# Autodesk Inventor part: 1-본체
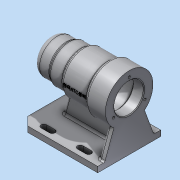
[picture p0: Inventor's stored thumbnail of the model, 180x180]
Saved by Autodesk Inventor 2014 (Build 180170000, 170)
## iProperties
Created: 2017-09
Part Number: 1-본체
Material: Aluminum 6061
Document SubType Name: Modeling
Designer: user
Density: 2.71 g/cm^3
Appearance: Aluminum - Flat
Mass: 697.162 g
Surface Area: 710.877 cm^2
Volume: 257.255 cm^3
Author: user
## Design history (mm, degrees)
sketch "Sketch1"
  geometry: L1 (0, 0)-(25, 0); L2 (25, 0)-(25, 25); L3 (25, 25)-(0, 25); L4 (0, 25)-(0, 0); L5 (25, 0)-(45, 0); L6 (45, 0)-(45, 27); L7 (45, 27)-(25, 27); L8 (25, 27)-(25, 0); L9 (45, 0)-(84, 0); L10 (84, 0)-(84, 30); L11 (84, 30)-(45, 30); L12 (45, 30)-(45, 0); L13 (84, 0)-(112, 0); L14 (112, 0)-(112, 34); L15 (112, 34)-(84, 34); L16 (84, 34)-(84, 0)
  constraints: 32 end point, 8 parallel, 4 horizontal, 4 perpendicular
  dimensions: "d0" = 25 distance between parallel lines of L2 L4; "d1" = 45 distance between parallel lines of L6 L4; "d2" = 84 distance between parallel lines of L10 L4; "d3" = 112 distance between parallel lines of L14 L4; "d4" = 60 diameter of L11 L9; "d5" = 54 diameter of L7 L5; "d6" = 50 diameter of L3 L1; "d7" = 68 diameter of L15 L13
revolve "Revolution1" sketch "Sketch1" stored, may be unused: angle "d8" = 90 deg
workplane "Work Plane1"
sketch "Sketch2"
  geometry: L1 (0, -45)-(-112, -45); L2 (-112, -45)-(-112, 45); L3 (-112, 45)-(0, 45); L4 (0, 45)-(0, -45); L5 (-112, 34)-(-112, -34) reference; 3 further points
  constraints: 8 end point, 3 midpoint, 2 parallel, 1 coincident, 1 horizontal, 1 perpendicular
  dimensions: "d10" = 112 distance of L1.start L1.end; "d11" = 90 distance of L1.end L2.end
extrude "Extrusion1" join sketch "Sketch2" distance "d12" = 8; taper "d13" = 0 deg
sketch "Sketch3"
  geometry: L1 (0, 45)-(0, -45) reference; L2 (112, -45)-(112, 45) reference; L3 (22, 4)-(112, 4); L4 (112, 4)-(112, -4); L5 (112, -4)-(22, -4); L6 (22, -4)-(22, 4); 2 further points
  constraints: 8 end point, 2 midpoint, 2 parallel, 1 horizontal, 1 perpendicular, 1 point on line
  dimensions: "d14" = 22 distance between parallel lines of L6 L1; "d15" = 8 distance of L5.end L3.start
extrude "Extrusion2" join sketch "Sketch3" stored distance "d16" = 8; taper "d17" = 0 deg
feature "FaceDraft1" dims angle "d18" = 15 deg
sketch "Sketch4"
  geometry: L1 (90, 0)-(90, 8) reference; L2 (49, 8)-(90, 8) reference; L3 (41, 8)-(41, 36.236) reference; L4 (0, 8)-(41, 8) reference; L5 (0, 0)-(0, 8) reference; L6 (10, 8)-(23.1, 43.992); L7 (80, 8)-(66.9, 43.992); L8 (49, 8)-(49, 36.236) reference; A1 r 34 centre (45, 70) between (49, 36.236) and (41, 36.236) reference
  constraints: 4 end point, 2 point on circle, 2 point on line
  dimensions: "d19" = 110 deg angle of L7 L2; "d20" = 110 deg angle of L4 L6; "d21" = 10 distance from line of L6.start L5; "d22" = 10 distance from line of L7.start L1
extrude "Extrusion5" join sketch "Sketch4" distance "d27" = 8; taper "d28" = 0 deg
chamfer "Chamfer1" distance "d29" = 12; stored, may be unused: second distance "d30" = 2, angle "d31" = 45 deg
sketch "Sketch5"
  geometry: L1 (112, -45)-(112, -35) reference; L2 (112, 45)-(12, 45) reference; L3 (76, -34)-(88, -34); L4 (76, -38)-(88, -38); L5 (88, -30)-(76, -30); L6 (24, -34)-(36, -34); L7 (36, -30)-(24, -30); L8 (24, -38)-(36, -38); L9 (76, 30)-(88, 30); L10 (76, 34)-(88, 34); L11 (88, 38)-(76, 38); L12 (24, 34)-(36, 34); L13 (24, 30)-(36, 30); L14 (36, 38)-(24, 38); A1 r 4 centre (76, -34) between (76, -30) and (76, -38); A2 r 4 centre (88, -34) between (88, -38) and (88, -30); A3 r 4 centre (36, -34) between (36, -38) and (36, -30); A4 r 4 centre (24, -34) between (24, -30) and (24, -38); A5 r 4 centre (76, 34) between (76, 38) and (76, 30); A6 r 4 centre (88, 34) between (88, 30) and (88, 38); A7 r 4 centre (36, 34) between (36, 30) and (36, 38); A8 r 4 centre (24, 34) between (24, 38) and (24, 30); 5 further points
  constraints: 32 end point, 16 point on circle, 16 tangent, 8 centre point, 5 horizontal alignment, 5 parallel, 4 midpoint, 2 vertical alignment
  dimensions: "d32" = 12 distance of L3.start L3.end; "d33" = 8 distance between parallel lines of L4 L5; "d34" = 12 distance of L6.start L6.end; "d35" = 8 distance between parallel lines of L8 L7; "d36" = 12 distance of L10.start L10.end; "d37" = 8 distance between parallel lines of L9 L11; "d38" = 12 distance of L12.start L12.end; "d39" = 8 distance between parallel lines of L13 L14; "d40" = 34 vertical distance of L12.start point (0, 0); "d41" = 34 vertical distance of L6.start point (0, 0); "d42" = 40 distance of L3.start L6.end; "d43" = 24 distance from line of L3.end L1
extrude "Extrusion6" cut sketch "Sketch5" stored distance "d44" = 8; taper "d45" = 0 deg
sketch "Sketch6"
  geometry: L1 (6, 10.5)-(9, 10.5); L2 (9, 10.5)-(9, 0); L3 (9, 0)-(6, 0); L4 (6, 0)-(6, 10.5); L5 (9, 0)-(13, 0); L6 (13, 0)-(13, 16); L7 (13, 16)-(9, 16); L8 (9, 16)-(9, 0); L9 (13, 0)-(31, 0); L10 (31, 0)-(31, 17.5); L11 (31, 17.5)-(13, 17.5); L12 (13, 17.5)-(13, 0); L13 (31, 0)-(43, 0); L14 (43, 0)-(43, 21); L15 (43, 21)-(31, 21); L16 (31, 21)-(31, 0); L17 (43, 0)-(97, 0); L18 (97, 0)-(97, 24); L19 (97, 24)-(43, 24); L20 (43, 24)-(43, 0); L21 (97, 0)-(112, 0); L22 (112, 0)-(112, 21); L23 (112, 21)-(97, 21); L24 (97, 21)-(97, 0); L25 (112, -26.008)-(112, 34) reference; 1 further point
  constraints: 48 end point, 12 parallel, 7 horizontal alignment, 6 horizontal, 6 perpendicular, 1 point on line
  dimensions: "d46" = 18 distance between parallel lines of L10 L12; "d47" = 12 distance between parallel lines of L14 L10; "d48" = 54 distance between parallel lines of L18 L20; "d49" = 15 distance between parallel lines of L22 L18; "d50" = 4 distance between parallel lines of L12 L8; "d51" = 3 distance between parallel lines of L8 L4; "d52" = 42 diameter of L23 L21; "d53" = 48 diameter of L19 L17; "d54" = 42 diameter of L15 L13; "d55" = 35 diameter of L11 L9; "d56" = 32 diameter of L7 L5; "d57" = 21 diameter of L1 L3; "d59" = 13 distance from line of L25.end L23
revolve "Revolution2" sketch "Sketch6" stored, may be unused: angle "d58" = 90 deg
fillet "Fillet1" dims "d60" = 9
fillet "Fillet2" dims "d62" = 0.3
fillet "Fillet3" dims "d63" = 3
chamfer "Chamfer2" distance "d64" = 1; stored, may be unused: second distance "d65" = 2, angle "d66" = 45 deg
sketch "Sketch7" dims "d67" = 52
  geometry: C1 r 22 at (45, 70) reference; 2 further points
  constraints: 1 coincident, 1 vertical alignment, 2 other
hole "Hole1" sketch "Sketch7" at (45, 96) diameter "d68" = 3.242; stored, may be unused: countersink angle "d72" = 90 deg, drill point angle "d74" = 118 deg; dims "d69" = 8, "d70" = 4, "d71" = 2, "d73" = 11
pattern_circular "Circular Pattern1" dims angle "d76" = 360 deg
fillet "Fillet4" dims "d78" = 3
fillet "Fillet5" dims "d79" = 3
fillet "Fillet6" dims "d80" = 3
workplane "Work Plane2"
sketch "Sketch8"
  geometry: L1 (45, 70)-(15, 70); A1 r 30 centre (45, 70) between (49, 40.268) and (41, 40.268) reference; 2 further points
  constraints: 2 end point, 1 coincident, 1 horizontal, 1 point on circle
workplane "Work Plane4"
sketch "Sketch10"
  geometry: L1 (-16, -29.732)-(-16, -29.732) reference; L2 (-16, -29.732)-(17, -29.732) reference; L3 (17, -29.732)-(17, -29.732) reference; L4 (17, -29.732)-(-16, -29.732) reference; 3 further points
  constraints: 1 coincident, 1 other
emboss "Emboss1" sketch "Sketch10" dims "d0" = 25, "d1" = 45, "d2" = 84, "d3" = 112, "d4" = 60, "d5" = 54, "d6" = 50, "d7" = 68, "d82" = 0.5, "d83" = 0
body "Solid1"
node "Projected Loop1"
other parameters: "d81" = -48
